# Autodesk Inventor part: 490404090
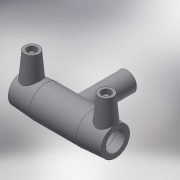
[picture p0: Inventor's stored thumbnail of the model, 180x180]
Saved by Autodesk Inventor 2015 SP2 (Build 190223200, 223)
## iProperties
Created: 2017-06
Part Number: 490404090
Material: Generic
Description: PLASSON TEE 90-90-90
Document SubType Name: Modeling
Designer: KIM
Mass: 57.3761 g
Surface Area: 241.06 cm^2
Volume: 57.3761 cm^3
Density: 1 g/cm^3
Appearance: Default
Author: KIM
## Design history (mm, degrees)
derived "490404.ipt"
feature "Solid1::490404.ipt"
tag "TaggingFeature1"
body "Solid1"
other parameters: "d0" = 294, "d2" = 113, "d3" = 71, "d4" = 73.5, "d5" = 101.7, "d6" = 85.5, "d8" = 168 deg, "d10" = 28.4, "d11" = 9.46667, "d13" = 294, "d14" = 17.6296, "d17" = 81, "d19" = 3.52592, "d20" = 168 deg, "d22" = 105.09, "d23" = 113, "d24" = 101.9373, "d25" = 135 deg, "d26" = 205.8, "d27" = 135 deg, "d29" = 71, "d30" = 15, "d31" = 117.6, "d34" = 5 deg, "d35" = 15, "d39" = 5 deg, "d40" = 9.6, "d41" = 4.8, "d42" = 6, "d43" = 0, "d45" = 4, "d46" = 14, "d47" = 0, "d48" = -137, "d51" = 0, "d52" = 72, "d54" = 0, "d55" = 101.7, "d56" = 113, "d57" = 102.9, "d58" = 135 deg, "d59" = 71, "d60" = 71, "d61" = 135 deg, "d62" = 137, "d72" = 133.77, "d73" = 66.885, "d74" = -137, "d75" = 94.5, "d77" = 0, "d78" = 72, "d80" = 0, "d82" = 80.5, "d83" = 0, "d84" = 3, "d85" = 0, "d86" = 3, "d87" = 0, "d88" = 20.59, "d89" = 5.1475, "d90" = 20.59, "L_" = 294, "L_1" = 71, "D_" = 113, "A_" = 71, "d_2" = 12, "H_" = 137
